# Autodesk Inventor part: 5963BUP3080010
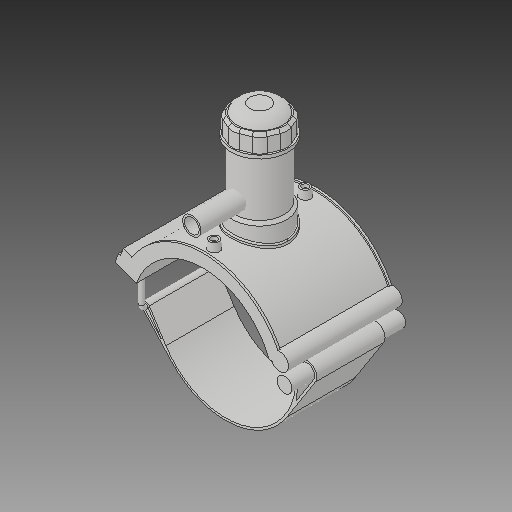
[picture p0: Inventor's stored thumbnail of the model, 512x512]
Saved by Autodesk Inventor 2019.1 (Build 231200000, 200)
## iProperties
Created: 2017-07
Part Number: 5963BUP3080010
Material: Generic
Description: PLASSON TAPPING SADDLE 8''IPS x 1''CTS
Document SubType Name: Modeling
Designer: KIM
Density: 1 g/cm^3
Appearance: Default
Author: KIM
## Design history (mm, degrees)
derived "5963BBP_5963BUP.ipt"
feature "Solid1::5963BBP_5963BUP.ipt"
feature "Solid2::5963BBP_5963BUP.ipt"
feature "Solid3::5963BBP_5963BUP.ipt"
tag "TaggingFeature1"
body "Solid1"
body "Solid2"
body "Solid3"
other parameters: "d0" = 218.7, "d2" = 269.748, "d3" = 54.675, "d4" = 176.022, "d5" = 0, "d6" = 0.1, "d8" = 0, "d19" = 6, "d20" = 6, "d21" = 105.6132, "d23" = 0, "d24" = 52.8066, "d26" = 0, "d27" = 3, "d28" = 3, "d29" = 3, "d30" = 72.9, "d31" = 6, "d32" = 0, "d33" = 0, "d34" = 0.6, "d40" = 131.91984, "d41" = 87.48, "d43" = 0, "d45" = 0, "d47" = 232.4592, "d70" = 15, "d72" = 0, "d73" = 6, "d75" = 5, "d76" = 0, "d77" = 10.935, "d78" = 139.35, "d79" = 15, "d80" = 70.4088, "d82" = 5 deg, "d84" = 4, "d85" = 14, "d86" = 0, "d87" = 3, "d88" = 0, "d89" = 1, "d90" = 1, "d91" = 140.8176, "d92" = 0, "d93" = 0.5, "d94" = 115.10526, "d96" = 258.76584, "d97" = 3.52044, "d98" = 0, "d102" = 2.187, "d120" = 140 deg, "d121" = 24.228, "d122" = 20 deg, "d123" = 507.384, "d124" = 152.2152, "d126" = 0, "d143" = 225.261, "d145" = 26.91692, "d149" = 3.2805, "d150" = 29.60862, "d153" = 176.022, "d154" = 0, "d156" = 126.846, "d157" = 160 deg, "d159" = 6.9984, "d161" = 3.2805, "d162" = 105.6132, "d163" = 0, "d164" = 109.35, "d167" = 21.87, "d168" = 123.7522, "d170" = 3.2805, "d172" = 0, "d173" = 1, "d175" = 109.35, "d176" = 20 deg, "d177" = 15.309, "d178" = 34.992, "d180" = 0, "d183" = 13.9968, "d184" = 12.2472, "d185" = 57.20715, "d186" = 57.20715, "d187" = 126.846, "d188" = 10.4976, "d189" = 15.309, "d190" = 0, "d191" = 190.269, "d193" = 6.9984, "d194" = 6.16077, "d195" = 90 deg, "d197" = 0, "d199" = 0, "d200" = 17.496, "d202" = 0, "d203" = 177.038, "d204" = 83.106, "d205" = 61.236, "d206" = 74.358, "d207" = 132.7785, "d208" = 138.08964, "d209" = 164.64534, "d210" = 75.2328, "d211" = 87.48, "d212" = 69.984, "d213" = 45.7191, "d216" = 0, "d217" = 21.87, "d218" = 21.87, "d219" = 4.374, "d222" = 218.7, "d224" = 0, "d225" = 65.024, "d226" = 28.45, "d227" = 22.76, "d228" = 104.902, "d230" = 4.374, "d_" = 218.7, "B_" = 179.832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
